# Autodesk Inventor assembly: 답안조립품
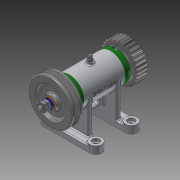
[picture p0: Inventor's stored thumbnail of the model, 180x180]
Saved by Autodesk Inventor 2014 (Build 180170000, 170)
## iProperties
Created: 2015-11
Part Number: 답안조립품
Document SubType Name: Assembly
Designer: SEC
Author: SEC
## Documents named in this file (16)
- C:\Users\SEC\Desktop\451109V1001\답안조립품.iam
- C:\Users\SEC\Desktop\451109V1001\1본체.ipt
- C:\Users\SEC\Desktop\451109V1001\커버.ipt
- C:\Users\SEC\Desktop\451109V1001\베어링 15 x 32 x 9.ipt
- C:\Users\SEC\Desktop\451109V1001\축.ipt
- C:\Users\SEC\Desktop\451109V1001\오일 실 15 25 7.ipt
- C:\Users\SEC\Desktop\451109V1001\볼트 M4 x 12.ipt
- C:\Users\SEC\Desktop\451109V1001\키 3 x 3 x 12.ipt
- C:\Users\SEC\Desktop\451109V1001\V벨트풀리.ipt
- C:\Users\SEC\Desktop\451109V1001\스퍼기어.ipt
- C:\Users\SEC\Desktop\451109V1001\와셔 8x17.ipt
- C:\Users\SEC\Desktop\451109V1001\스프링와셔 8.ipt
- C:\Users\SEC\Desktop\451109V1001\너트 M 8.ipt
- C:\Users\SEC\Desktop\451109V1001\와셔 6x11.5.ipt
- C:\Users\SEC\Desktop\451109V1001\볼트 M 6 x 8.ipt
- C:\Users\SEC\Desktop\451109V1001\니플 M 6 x 0.75.ipt
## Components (12 placed, 4 different names)
1. 1본체:1
2. KS B 2023 6002 - 15 x 32 x 9:1
3. KS B 2023 6002 - 15 x 32 x 9:2
4. V벨트풀리:1 — 각도:3
5. ISO 4762 M4 x 12:1
6. ISO 4762 M4 x 12:3
7. ISO 4762 M4 x 12:4
8. ISO 4762 M4 x 12:5
9. ISO 4762 M4 x 12:2
10. ISO 4762 M4 x 12:6
11. ISO 4762 M4 x 12:7
12. ISO 4762 M4 x 12:8
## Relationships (1: Angle 1)
- 각도:3 [Angle]: V벨트풀리:1
